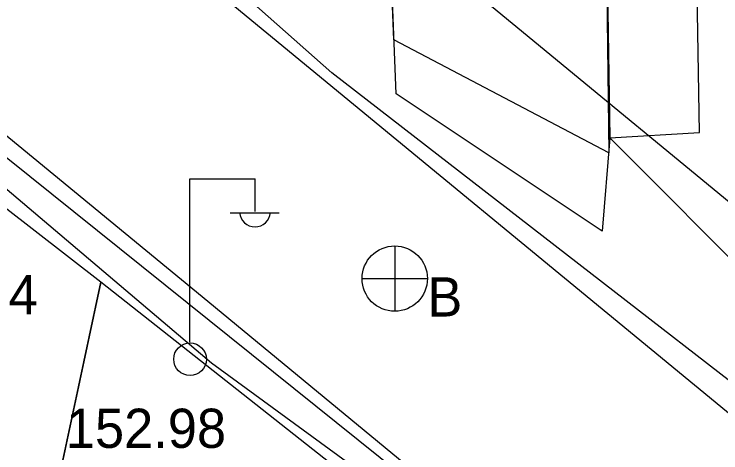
# Model space of a CAD drawing. Extents: x 419677 to 421689, y 4450851 to 4452923.
# Drawn here: x 420402.9 to 420424.55, y 4452065.4 to 4452078.82 of the extents above; entities that cross this region are included whole.
import ezdxf

# ---------------------------------------------------------------- set-up
doc = ezdxf.new("R2010")
doc.units = 0
for name, color, linetype in [('AA_HH', 7, 'Continuous'), ('Level 10', 7, 'Continuous'), ('Level 29', 7, 'Continuous'), ('Level 62', 7, 'Continuous')]:
    doc.layers.add(name, color=color, linetype=linetype)

msp = doc.modelspace()

# ---------------------------------------------------------------- linework, layer by layer
at = {"layer": 'AA_HH'}
for p, q in [((420408.28, 4452068.786), (420408.28, 4452073.786)), ((420408.28, 4452073.786), (420410.28, 4452073.786)), ((420410.28, 4452072.786), (420410.28, 4452073.786)), ((420409.52, 4452072.746), (420411.02, 4452072.746)), ((420414.558, 4452071.73), (420414.558, 4452069.73)), ((420413.558, 4452070.73), (420415.558, 4452070.73))]:
    msp.add_line(p, q, dxfattribs=at)
for points in [[(420317.236, 4452103.177), (420337.405, 4452116.594), (420344.369, 4452120.618), (420344.658, 4452120.664), (420379.054, 4452093.495), (420408.951, 4452068.147), (420424.16, 4452057.043), (420424.384, 4452056.89), (420424.576, 4452056.652), (420424.822, 4452056.326), (420423.72, 4452053.785)], [(420433.878, 4452060.578), (420412.635, 4452077.028), (420400.032, 4452088.163), (420406.057, 4452089.829), (420410.576, 4452090.158)]]:
    msp.add_lwpolyline(points, dxfattribs=at)
for points in [[(420414.598, 4452076.388), (420414.058, 4452090.075), (420420.876, 4452090.71), (420420.913, 4452089.456), (420421.149, 4452075.039), (420420.913, 4452072.184)], [(420420.913, 4452089.456), (420426.889, 4452090.253), (420427.345, 4452072.134), (420425.853, 4452070.328), (420421.149, 4452075.039)], [(420423.671, 4452088.671), (420420.928, 4452088.577), (420421.149, 4452075.039), (420423.888, 4452075.205)], [(420414.217, 4452086.029), (420417.43, 4452086.13), (420417.382, 4452084.877), (420420.983, 4452085.174), (420421.111, 4452074.574), (420414.532, 4452078.042)], [(420405.557, 4452070.621), (420393.388, 4452080.065), (420388.529, 4452064.834), (420403.311, 4452060.104)], [(420405.557, 4452070.621), (420403.18, 4452059.491), (420406.243, 4452058.878), (420406.077, 4452058.124), (420421.999, 4452051.5), (420424.009, 4452056.065)]]:
    msp.add_lwpolyline(points, close=True, dxfattribs=at)
for centre, radius in [((420414.558, 4452070.73), 1), ((420408.29, 4452068.261), 0.5)]:
    msp.add_circle(centre, radius, dxfattribs=at)
msp.add_arc((420410.28, 4452072.789), 0.474, 184.8384, 355.1464, dxfattribs=at)
at = {"layer": 'Level 10'}
for points in [[(420408.198, 4452069.984), (420345.402, 4452120.383), (420315.25, 4452102.126), (420310.494, 4452088.921)], [(420408.198, 4452069.984), (420408.198, 4452069.984)], [(420449.694, 4452025.96), (420455.779, 4452025.884), (420458.652, 4452029.491), (420408.198, 4452069.984)]]:
    msp.add_lwpolyline(points, dxfattribs=at)
at = {"layer": 'Level 29'}
msp.add_lwpolyline([(420460.864, 4452043.387), (420414.222, 4452081.778), (420414.123, 4452084.574), (420421.216, 4452085.177)], dxfattribs=at)
at = {"layer": 'Level 62'}
for p, q in [((420408.658, 4452070.167), (420355.096, 4452114.255)), ((420458.678, 4452038.71), (420409.061, 4452079.55)), ((420456.68, 4452030.64), (420408.658, 4452070.168)), ((420408.658, 4452070.167), (420408.658, 4452070.167)), ((420408.658, 4452070.167), (420408.658, 4452070.167)), ((420408.658, 4452070.167), (420408.658, 4452070.167))]:
    msp.add_line(p, q, dxfattribs=at)

# ---------------------------------------------------------------- texts
at = {"layer": 'AA_HH'}
for s, p in [('155.74', (420398.717, 4452069.638)), ('B', (420415.558, 4452069.569)), ('152.98', (420404.486, 4452065.548))]:
    msp.add_text(s, height=1.2, dxfattribs=at).set_placement(p)

doc.saveas('drawing.dxf')
